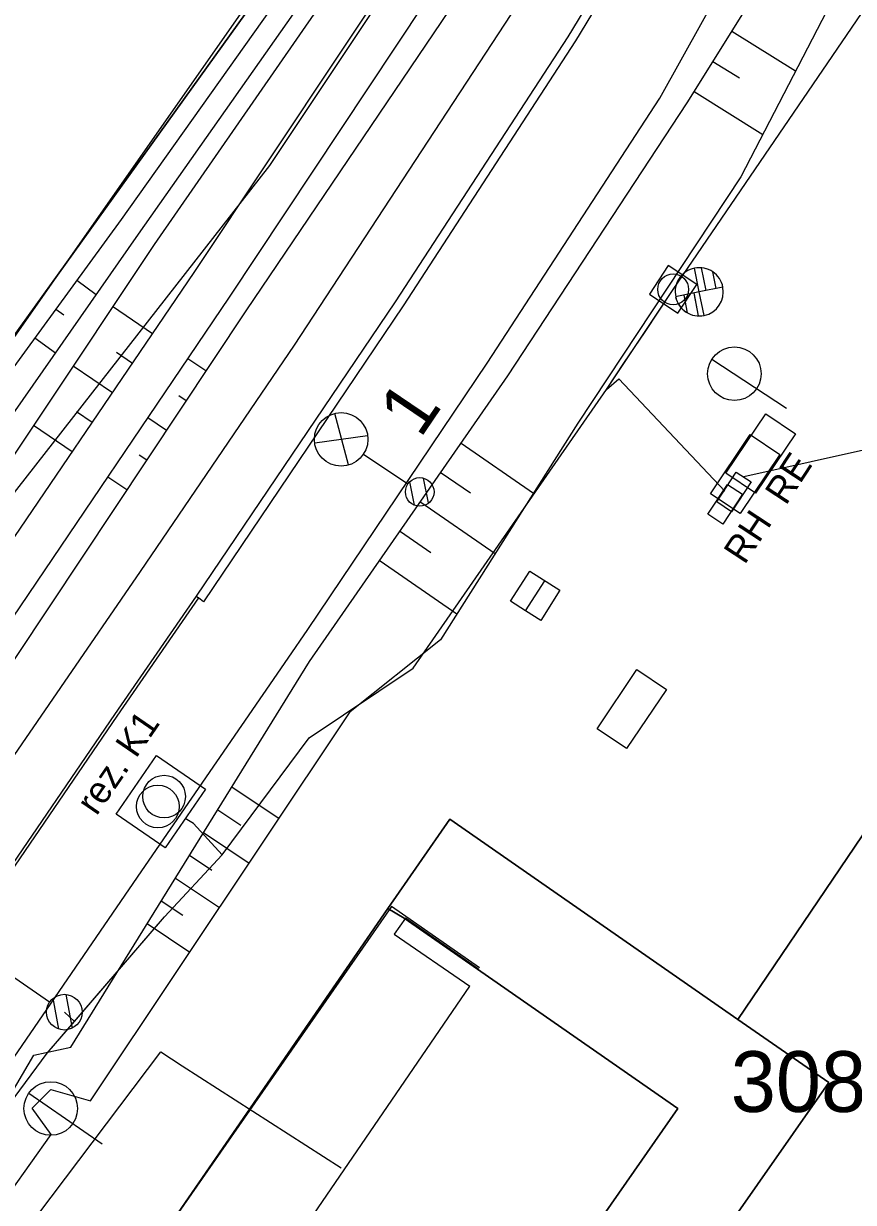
# Model space of a CAD drawing. Extents: x -558195 to -557985, y -1073457 to -1073198.
# Drawn here: x -558098.53 to -558075.28, y -1073355.93 to -1073322.92 of the extents above; entities that cross this region are included whole.
import ezdxf

# ---------------------------------------------------------------- set-up
doc = ezdxf.new("R2010")
doc.units = 0
for name, color, linetype in [('DWG-zabzař', 7, 'Continuous'), ('El2015-Elektro nadzemní', 7, 'Continuous'), ('El2015-Elektro podzemní', 7, 'Continuous'), ('El2015-Nástupiště', 7, 'Continuous'), ('El2015-Sdělovací dálkové podzemní', 7, 'Continuous'), ('El2015-Sdělovací místní podzemní', 7, 'Continuous'), ('El2015-Sdělovací objekt', 7, 'Continuous'), ('El2015-Sonda - šrafa - vrstevnice', 7, 'Continuous'), ('El2015-Terén', 7, 'Continuous'), ('Elektro nadzemní', 7, 'Continuous'), ('Kanalizace nadzemní', 7, 'Continuous'), ('Kolej', 7, 'Continuous'), ('Nástupiště', 7, 'Continuous'), ('Plot - zábradlí', 7, 'Continuous'), ('Přejezd - štěrkové lože', 7, 'Continuous'), ('Sonda - šrafa - vrstevnice', 7, 'Continuous'), ('Stavba', 7, 'Continuous'), ('Svazek obcí údolí Desné', 7, 'Continuous'), ('Svazek obcí-elektro', 7, 'Continuous'), ('Svazek obcí-sdělovací', 7, 'Continuous'), ('Svazek obcí-zabezpečovací', 7, 'Continuous'), ('Terén', 7, 'Continuous'), ('trasa_NN_popisky', 7, 'Continuous'), ('Vedení nerozlišené', 7, 'Continuous'), ('Vedení neurčené', 7, 'Continuous'), ('Vrstva 15', 7, 'Continuous'), ('Vrstva 16', 7, 'Continuous'), ('Vrstva 18', 7, 'Continuous')]:
    doc.layers.add(name, color=color, linetype=linetype)

# ---------------------------------------------------------------- blocks, each defined once
blk = doc.blocks.new('C161_1')
at = {"layer": 'El2015-Sdělovací místní podzemní'}
blk.add_lwpolyline([(-19.93, 33.22), (19.93, 33.22), (19.93, 0), (-19.93, 0)], close=True, dxfattribs=at)
for centre in [(-3.21, 16.51), (3.37, 16.75)]:
    blk.add_circle(centre, 11.96, dxfattribs=at)
blk = doc.blocks.new('C730_1')
at = {"layer": 'El2015-Sdělovací objekt'}
blk.add_lwpolyline([(-9.6, -9.6), (9.6, -9.6), (9.6, 9.6), (-9.6, 9.6)], close=True, dxfattribs=at)
blk.add_circle((0, 0), 8.64, dxfattribs=at)
blk = doc.blocks.new('C178')
at = {"layer": 'El2015-Sdělovací dálkové podzemní'}
for p, q in [((-13.55, -0.04), (-6.78, 6.73)), ((2.2, -2.24), (11.44, 7)), ((-11.88, -6.47), (-2.77, 2.68)), ((6.29, -6.25), (13.38, 0.84))]:
    blk.add_line(p, q, dxfattribs=at)
for points in [[(-9.57, 9.62), (-9.55, 9.59), (-0.13, 0), (-9.72, -9.5)], [(9.46, 9.59), (-0.04, 0), (9.55, -9.5), (9.56, -9.48)], [(9.44, 9.62), (9.46, 9.59)]]:
    blk.add_lwpolyline(points, dxfattribs=at)
for centre, radius, start, end in [((-0.01, 0.01), 13.48, 45.47613, 134.84216), ((-0.11, 0.01), 13.48, 134.52387, 224.76094), ((-0.01, 0.01), 13.48, 315.23906, 45.47613), ((-0.11, 0.01), 13.5, 224.76226, 315.55166)]:
    blk.add_arc(centre, radius, start, end, dxfattribs=at)

msp = doc.modelspace()

# ---------------------------------------------------------------- linework, layer by layer
at = {"layer": 'DWG-zabzař'}
for p, q in [((-558084.66, -1073316.4), (-558091.64, -1073326.89)), ((-558091.64, -1073326.89), (-558100.51, -1073338.24)), ((-558098.13, -1073356.28), (-558094.69, -1073351.72)), ((-558094.69, -1073351.72), (-558094.09, -1073352.11)), ((-558094.09, -1073352.11), (-558089.64, -1073354.97))]:
    msp.add_line(p, q, dxfattribs=at)
at = {"layer": 'El2015-Elektro nadzemní'}
for p, q in [((-558097.804, -1073350.323), (-558100.689, -1073348.34)), ((-558097.542, -1073351.083), (-558097.703, -1073350.218)), ((-558097.167, -1073351.05), (-558097.342, -1073350.109))]:
    msp.add_line(p, q, dxfattribs=at)
for points in [[(-558078.564, -1073335.479), (-558078.146, -1073335.753), (-558078.694, -1073336.589), (-558079.112, -1073336.315), (-558078.564, -1073335.479)], [(-558078.81, -1073335.827), (-558078.392, -1073336.101), (-558078.94, -1073336.937), (-558079.358, -1073336.663), (-558078.81, -1073335.827)]]:
    msp.add_lwpolyline(points, dxfattribs=at)
msp.add_circle((-558097.392, -1073350.606), 0.5, dxfattribs=at)
at = {"layer": 'El2015-Elektro podzemní'}
msp.add_line((-558097.108, -1073350.87), (-558097.392, -1073350.606), dxfattribs=at)
at = {"layer": 'El2015-Nástupiště'}
for points in [[(-558093.699, -1073338.955), (-558095.987, -1073342.272), (-558099.388, -1073347.237), (-558102.768, -1073352.161)], [(-558093.633, -1073339), (-558095.921, -1073342.317), (-558099.322, -1073347.282)], [(-558093.699, -1073338.955), (-558093.633, -1073339), (-558093.633, -1073339)], [(-558100.191, -1073353.885), (-558095.119, -1073346.503), (-558091.122, -1073340.69), (-558090.573, -1073339.885)]]:
    msp.add_lwpolyline(points, dxfattribs=at)
at = {"layer": 'El2015-Sdělovací dálkové podzemní'}
for p, q in [((-558079.731, -1073329.767), (-558079.731, -1073329.767)), ((-558079.545, -1073329.761), (-558079.416, -1073330.394)), ((-558079.231, -1073329.869), (-558079.136, -1073330.338)), ((-558080.038, -1073330.524), (-558079.939, -1073331.016)), ((-558079.758, -1073330.465), (-558079.628, -1073331.105)), ((-558079.466, -1073331.094), (-558079.466, -1073331.094))]:
    msp.add_line(p, q, dxfattribs=at)
for points in [[(-558078.941, -1073330.302), (-558079.6, -1073330.43), (-558079.731, -1073329.767)], [(-558079.466, -1073331.094), (-558079.603, -1073330.433), (-558080.264, -1073330.571)]]:
    msp.add_lwpolyline(points, dxfattribs=at)
for centre, radius, start, end in [((-558079.6, -1073330.43), 0.675, 101.2251, 192.0145), ((-558079.6, -1073330.43), 0.674, 10.9867, 101.2237), ((-558079.603, -1073330.435), 0.674, 191.7019, 281.9389), ((-558079.603, -1073330.435), 0.674, 281.9389, 11.305)]:
    msp.add_arc(centre, radius, start, end, dxfattribs=at)
at = {"layer": 'El2015-Sdělovací objekt'}
msp.add_lwpolyline([(-558080.469, -1073329.699), (-558080.999, -1073330.499), (-558080.199, -1073331.029), (-558079.669, -1073330.229)], close=True, dxfattribs=at)
msp.add_circle((-558080.334, -1073330.364), 0.432, dxfattribs=at)
at = {"layer": 'El2015-Sonda - šrafa - vrstevnice'}
for p, q in [((-558092.7, -1073344.297), (-558091.376, -1073345.182)), ((-558093.095, -1073344.935), (-558092.444, -1073345.37)), ((-558093.491, -1073345.573), (-558092.209, -1073346.429)), ((-558093.886, -1073346.211), (-558093.256, -1073346.632)), ((-558094.281, -1073346.849), (-558093.043, -1073347.676)), ((-558094.676, -1073347.487), (-558094.068, -1073347.893)), ((-558095.071, -1073348.125), (-558093.876, -1073348.924))]:
    msp.add_line(p, q, dxfattribs=at)
at = {"layer": 'El2015-Terén'}
for points in [[(-558100.191, -1073353.885), (-558100.042, -1073354.758), (-558099.266, -1073353.898), (-558099.045, -1073353.167), (-558098.244, -1073351.807), (-558097.213, -1073351.582), (-558090.522, -1073340.781)], [(-558100.875, -1073354.883), (-558100.587, -1073355.931), (-558098.897, -1073355.64), (-558097.764, -1073354.03), (-558098.294, -1073353.295), (-558097.774, -1073352.77), (-558096.662, -1073353.093), (-558089.38, -1073342.195)]]:
    msp.add_lwpolyline(points, dxfattribs=at)
at = {"layer": 'Elektro nadzemní'}
for p, q in [((-558089.426, -1073335.278), (-558089.81, -1073333.836)), ((-558090.373, -1073334.661), (-558088.896, -1073334.455)), ((-558089.012, -1073334.978), (-558087.766, -1073335.813)), ((-558087.584, -1073336.404), (-558087.713, -1073335.753)), ((-558087.188, -1073336.346), (-558087.325, -1073335.653))]:
    msp.add_line(p, q, dxfattribs=at)
for points in [[(-558078.024, -1073336.07), (-558078.854, -1073335.511), (-558077.736, -1073333.852), (-558076.906, -1073334.411), (-558078.024, -1073336.07)], [(-558078.46, -1073336.644), (-558079.29, -1073336.085), (-558078.172, -1073334.426), (-558077.342, -1073334.985), (-558078.46, -1073336.644)], [(-558081.637, -1073343.226), (-558082.467, -1073342.667), (-558081.349, -1073341.008), (-558080.519, -1073341.567), (-558081.637, -1073343.226)]]:
    msp.add_lwpolyline(points, dxfattribs=at)
for centre, radius in [((-558089.636, -1073334.564), 0.749), ((-558087.434, -1073336.036), 0.4), ((-558087.434, -1073336.036), 0.4)]:
    msp.add_circle(centre, radius, dxfattribs=at)
at = {"layer": 'Kanalizace nadzemní'}
msp.add_lwpolyline([(-558084.466, -1073339.369), (-558084.889, -1073339.1), (-558084.352, -1073338.255), (-558083.507, -1073338.792), (-558084.044, -1073339.637), (-558084.466, -1073339.369), (-558083.93, -1073338.523)], dxfattribs=at)
at = {"layer": 'Kolej'}
msp.add_lwpolyline([(-558162.085, -1073435.464), (-558155.66, -1073426.127), (-558147.216, -1073413.854), (-558143.692, -1073408.727), (-558141.06, -1073404.904), (-558137.302, -1073399.438), (-558134.569, -1073395.461), (-558131.717, -1073391.307), (-558124.893, -1073381.375), (-558115.4, -1073367.564), (-558106.183, -1073354.164), (-558097.487, -1073341.511), (-558095.261, -1073338.268), (-558090.946, -1073331.927), (-558084.696, -1073322.399), (-558079.035, -1073313.091), (-558076.876, -1073309.237)], dxfattribs=at)
at = {"layer": 'Nástupiště'}
for points in [[(-558075.504, -1073310.182), (-558077.642, -1073314), (-558083.287, -1073323.291), (-558088.119, -1073330.713), (-558093.699, -1073338.955)], [(-558075.301, -1073310.322), (-558077.424, -1073314.112), (-558083.069, -1073323.403), (-558087.901, -1073330.825), (-558093.497, -1073339.112), (-558093.633, -1073339)], [(-558090.573, -1073339.885), (-558085.54, -1073332.431), (-558080.709, -1073325.01), (-558077.164, -1073318.639)]]:
    msp.add_lwpolyline(points, dxfattribs=at)
at = {"layer": 'Plot - zábradlí'}
msp.add_lwpolyline([(-558081.585, -1073305.993), (-558081.958, -1073306.712), (-558085.995, -1073313.64), (-558091.417, -1073321.151), (-558105.2, -1073340.829), (-558131.731, -1073378.073), (-558133.048, -1073381.894), (-558138.367, -1073389.952)], dxfattribs=at)
at = {"layer": 'Přejezd - štěrkové lože'}
for p, q in [((-558093.424, -1073332.648), (-558093.935, -1073332.308)), ((-558093.977, -1073333.481), (-558094.185, -1073333.343)), ((-558094.531, -1073334.314), (-558095.056, -1073333.965)), ((-558095.085, -1073335.147), (-558095.298, -1073335.005)), ((-558095.638, -1073335.979), (-558096.177, -1073335.621))]:
    msp.add_line(p, q, dxfattribs=at)
for points in [[(-558134.688, -1073392.469), (-558133.239, -1073389.979), (-558128.353, -1073382.563), (-558117.195, -1073366.537), (-558107.127, -1073351.64), (-558099.301, -1073340.237), (-558092.768, -1073330.583), (-558086.524, -1073321.182), (-558080.801, -1073311.959), (-558078.61, -1073308.043)], [(-558078.156, -1073308.355), (-558080.336, -1073312.26), (-558085.948, -1073321.555), (-558092.305, -1073330.965), (-558098.739, -1073340.644), (-558106.694, -1073352.203), (-558116.612, -1073366.808), (-558126.104, -1073380.52), (-558132.827, -1073390.228), (-558134.688, -1073392.469)]]:
    msp.add_lwpolyline(points, dxfattribs=at)
at = {"layer": 'Sonda - šrafa - vrstevnice'}
for p, q in [((-558078.687, -1073323.129), (-558076.903, -1073324.243)), ((-558079.217, -1073323.978), (-558078.475, -1073324.44)), ((-558079.746, -1073324.826), (-558077.825, -1073326.025)), ((-558097.04, -1073330.107), (-558096.498, -1073330.503)), ((-558097.629, -1073330.916), (-558097.406, -1073331.078)), ((-558094.921, -1073331.608), (-558096.038, -1073330.847)), ((-558098.219, -1073331.723), (-558097.644, -1073332.143)), ((-558095.484, -1073332.435), (-558095.927, -1073332.133)), ((-558096.047, -1073333.261), (-558097.148, -1073332.511)), ((-558096.61, -1073334.088), (-558097.047, -1073333.79)), ((-558097.173, -1073334.914), (-558098.259, -1073334.175)), ((-558086.269, -1073334.674), (-558084.247, -1073336.072)), ((-558086.838, -1073335.497), (-558086.016, -1073336.065)), ((-558087.407, -1073336.319), (-558085.319, -1073337.763)), ((-558087.976, -1073337.141), (-558087.127, -1073337.728)), ((-558088.544, -1073337.964), (-558086.391, -1073339.453))]:
    msp.add_line(p, q, dxfattribs=at)
at = {"layer": 'Stavba'}
for points in [[(-558085.764, -1073349.362), (-558088.225, -1073347.646), (-558094.346, -1073356.427), (-558098.392, -1073362.333)], [(-558087.829, -1073347.978), (-558088.146, -1073348.417), (-558086.033, -1073349.879)], [(-558085.79, -1073349.4), (-558087.829, -1073347.978)], [(-558094.346, -1073356.427), (-558091.741, -1073358.211), (-558086.033, -1073349.879)]]:
    msp.add_lwpolyline(points, dxfattribs=at)
at = {"layer": 'Svazek obcí údolí Desné'}
for points in [[(-558167.537, -1073431.708), (-558157.08, -1073415.91), (-558144.45, -1073397.61), (-558143.83, -1073396.83), (-558140.29, -1073392.34), (-558139.67, -1073391.56), (-558138.4, -1073389.94), (-558132.32, -1073380.12), (-558131.71, -1073378.11), (-558099.53, -1073332.65), (-558091.21, -1073321.1), (-558086.89, -1073315.11), (-558086.02, -1073313.63), (-558082.18, -1073306.93), (-558081.607, -1073305.978)], [(-558060.859, -1073320.27), (-558066.64, -1073329.29), (-558067.37, -1073328.67), (-558071.91, -1073335.47), (-558071.45, -1073339.78), (-558072.38, -1073341.74), (-558078.52, -1073350.81), (-558086.59, -1073345.2), (-558088.33, -1073347.7), (-558094.78, -1073357.07), (-558098.42, -1073362.32), (-558098.04, -1073362.58), (-558100.88, -1073366.68), (-558101.24, -1073366.41), (-558106.08, -1073373.34), (-558109.37, -1073371.06), (-558120.48, -1073382.36), (-558123.3, -1073385.22), (-558134.85, -1073401.19), (-558135.09, -1073403.23), (-558138.47, -1073412.32), (-558157.115, -1073438.887)]]:
    msp.add_lwpolyline(points, dxfattribs=at)
at = {"layer": 'Svazek obcí-elektro'}
for p, q in [((-558097.804, -1073350.323), (-558100.689, -1073348.34)), ((-558097.542, -1073351.083), (-558097.703, -1073350.218)), ((-558097.167, -1073351.05), (-558097.342, -1073350.109))]:
    msp.add_line(p, q, dxfattribs=at)
msp.add_lwpolyline([(-558104.377, -1073360.537), (-558097.871, -1073351.756), (-558097.108, -1073350.87), (-558094.584, -1073347.94), (-558092.974, -1073346.202), (-558090.533, -1073342.919), (-558087.618, -1073340.975), (-558082.203, -1073333.171), (-558081.857, -1073332.87), (-558078.884, -1073336.019)], dxfattribs=at)
msp.add_lwpolyline([(-558104.377, -1073360.537), (-558097.871, -1073351.756), (-558097.108, -1073350.87), (-558094.584, -1073347.94), (-558092.974, -1073346.202), (-558090.533, -1073342.919), (-558087.618, -1073340.975), (-558082.203, -1073333.171), (-558081.857, -1073332.87), (-558078.884, -1073336.019)], dxfattribs=at)
msp.add_circle((-558097.392, -1073350.606), 0.5, dxfattribs=at)
at = {"layer": 'Svazek obcí-sdělovací'}
msp.add_line((-558081.857, -1073332.87), (-558078.884, -1073336.019), dxfattribs=at)
for points in [[(-558092.974, -1073346.202), (-558090.533, -1073342.919), (-558087.618, -1073340.975), (-558082.203, -1073333.171), (-558080.334, -1073330.364), (-558074.513, -1073321.837), (-558069.419, -1073314.373)], [(-558092.974, -1073346.202), (-558093.77, -1073345.321), (-558094.003, -1073345.183)]]:
    msp.add_lwpolyline(points, dxfattribs=at)
at = {"layer": 'Svazek obcí-zabezpečovací'}
msp.add_lwpolyline([(-558104.377, -1073360.537), (-558097.871, -1073351.756), (-558094.584, -1073347.94), (-558092.974, -1073346.202), (-558090.533, -1073342.919), (-558087.618, -1073340.975), (-558082.203, -1073333.171), (-558081.697, -1073332.405), (-558081.138, -1073331.577), (-558080.334, -1073330.364), (-558074.513, -1073321.837)], dxfattribs=at)
at = {"layer": 'Terén'}
for points in [[(-558081.18, -1073306.272), (-558083.456, -1073310.395), (-558089.337, -1073319.304), (-558095.797, -1073328.403), (-558102.651, -1073337.801)], [(-558080.693, -1073306.608), (-558082.815, -1073310.544), (-558088.899, -1073319.675), (-558095.32, -1073328.817), (-558102.006, -1073338.385), (-558110.752, -1073350.405)], [(-558080.325, -1073306.861), (-558082.46, -1073310.779), (-558088.525, -1073319.94), (-558094.874, -1073329.104), (-558101.386, -1073338.86), (-558109.505, -1073351.261), (-558119.112, -1073365.018), (-558130.44, -1073381.204), (-558136.541, -1073389.319), (-558138.367, -1073389.952)], [(-558141.446, -1073388.086), (-558138.672, -1073391.073), (-558136.007, -1073391.106), (-558129.583, -1073381.786), (-558118.096, -1073365.959), (-558108.152, -1073351.289), (-558100.315, -1073339.526), (-558093.751, -1073329.892), (-558087.503, -1073320.498), (-558081.802, -1073311.451), (-558079.554, -1073307.392)], [(-558075.447, -1073319.704), (-558075.635, -1073321.794), (-558078.439, -1073327.212), (-558083.002, -1073334.109), (-558086.852, -1073340.18), (-558089.38, -1073342.195)], [(-558090.522, -1073340.781), (-558084.963, -1073332.785), (-558079.942, -1073325.14), (-558076.703, -1073319.95)]]:
    msp.add_lwpolyline(points, dxfattribs=at)
at = {"layer": 'trasa_NN_popisky'}
msp.add_lwpolyline([(-558056.317, -1073323.399), (-558061.372, -1073331.828), (-558078.355, -1073335.616)], dxfattribs=at)
at = {"layer": 'Vedení nerozlišené'}
for p, q in [((-558079.245, -1073332.315), (-558077.155, -1073333.686)), ((-558098.391, -1073352.878), (-558096.331, -1073354.294))]:
    msp.add_line(p, q, dxfattribs=at)
for centre in [(-558078.618, -1073332.726), (-558097.773, -1073353.303)]:
    msp.add_circle(centre, 0.75, dxfattribs=at)
at = {"layer": 'Vrstva 15'}
for points in [[(-558167.537, -1073431.708), (-558157.08, -1073415.91), (-558144.45, -1073397.61), (-558143.83, -1073396.83), (-558140.29, -1073392.34), (-558139.67, -1073391.56), (-558138.4, -1073389.94), (-558132.32, -1073380.12), (-558131.71, -1073378.11), (-558099.53, -1073332.65), (-558091.21, -1073321.1), (-558086.89, -1073315.11), (-558086.02, -1073313.63), (-558082.18, -1073306.93), (-558081.607, -1073305.978)], [(-558060.859, -1073320.27), (-558066.64, -1073329.29), (-558067.37, -1073328.67), (-558071.91, -1073335.47), (-558071.45, -1073339.78), (-558072.38, -1073341.74), (-558078.52, -1073350.81), (-558086.59, -1073345.2), (-558088.33, -1073347.7), (-558094.78, -1073357.07), (-558098.42, -1073362.32), (-558098.04, -1073362.58), (-558100.88, -1073366.68), (-558101.24, -1073366.41), (-558106.08, -1073373.34), (-558109.37, -1073371.06), (-558120.48, -1073382.36), (-558123.3, -1073385.22), (-558134.85, -1073401.19), (-558135.09, -1073403.23), (-558138.47, -1073412.32), (-558157.115, -1073438.887)], [(-558056.484, -1073323.284), (-558060.65, -1073327.54), (-558061.08, -1073328.44), (-558065.9, -1073348.86), (-558066.74, -1073350.64), (-558083.8, -1073372.96), (-558092.4, -1073382.52), (-558096.11, -1073380.17), (-558087.9, -1073369.62), (-558075.97, -1073352.58), (-558078.52, -1073350.81), (-558072.38, -1073341.74), (-558071.45, -1073339.78), (-558071.91, -1073335.47), (-558067.37, -1073328.67), (-558066.64, -1073329.29), (-558060.859, -1073320.27)]]:
    msp.add_lwpolyline(points, dxfattribs=at)
for points in [[(-558139.67, -1073391.56), (-558140.9, -1073387.37), (-558143.89, -1073378.07), (-558101.27, -1073319.14), (-558106.1, -1073313.94), (-558108.58, -1073311.13), (-558110.09, -1073309.68), (-558108.61, -1073307.47), (-558103.03, -1073311.24), (-558100.91, -1073308.09), (-558098.7, -1073309.62), (-558100.86, -1073312.72), (-558101.25, -1073313.61), (-558091.21, -1073321.1), (-558099.53, -1073332.65), (-558131.71, -1073378.11), (-558132.32, -1073380.12), (-558138.4, -1073389.94)], [(-558086.24, -1073361.96), (-558080.2, -1073353.3), (-558087.87, -1073347.97), (-558088.33, -1073347.7), (-558086.59, -1073345.2), (-558078.52, -1073350.81), (-558075.97, -1073352.58), (-558087.9, -1073369.62), (-558096.11, -1073380.17), (-558097.38, -1073379.37), (-558101.16, -1073376.75), (-558106.08, -1073373.34), (-558101.24, -1073366.41), (-558100.88, -1073366.68), (-558093.95, -1073371.49), (-558091.09, -1073367.38), (-558089.54, -1073368.47), (-558085.38, -1073362.53)], [(-558094.78, -1073357.07), (-558088.33, -1073347.7), (-558087.87, -1073347.97), (-558080.2, -1073353.3), (-558086.24, -1073361.96), (-558085.38, -1073362.53), (-558089.54, -1073368.47), (-558091.09, -1073367.38), (-558093.95, -1073371.49), (-558100.88, -1073366.68), (-558098.04, -1073362.58), (-558098.42, -1073362.32)]]:
    msp.add_lwpolyline(points, close=True, dxfattribs=at)
at = {"layer": 'Vrstva 16'}
msp.add_lwpolyline([(-558098.42, -1073362.32), (-558094.78, -1073357.07), (-558088.33, -1073347.7), (-558087.87, -1073347.97), (-558080.2, -1073353.3), (-558086.24, -1073361.96), (-558085.38, -1073362.53), (-558089.54, -1073368.47), (-558091.09, -1073367.38), (-558093.95, -1073371.49), (-558100.88, -1073366.68), (-558098.04, -1073362.58)], close=True, dxfattribs=at)

# ---------------------------------------------------------------- block references
at = {"layer": 'Svazek obcí-sdělovací'}
for name, p, xscale, yscale, rotation in [('C178', (-558079.604, -1073330.435), 0.05, 0.05000000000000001, -123.53719177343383), ('C730_1', (-558080.334, -1073330.364), 0.05, 0.05000000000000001, -123.53719162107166), ('C161_1', (-558094.003, -1073345.183), 0.049999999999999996, 0.05, 55.50051041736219)]:
    msp.add_blockref(name, p, dxfattribs=dict(at, xscale=xscale, yscale=yscale, rotation=rotation))

# ---------------------------------------------------------------- texts
at = {"layer": 'El2015-Elektro nadzemní'}
for s, p in [('RE', (-558077.176, -1073336.437)), ('RH', (-558078.332, -1073338.097))]:
    msp.add_text(s, height=0.75, rotation=56.7367, dxfattribs=at).set_placement(p)
at = {"layer": 'Svazek obcí-sdělovací'}
msp.add_text('rez. K1', height=0.75, rotation=55.5005, dxfattribs=at).set_placement((-558096.491, -1073345.129))
at = {"layer": 'Vedení neurčené'}
msp.add_text('1', height=1.5, rotation=55.8849, dxfattribs=at).set_placement((-558087.419, -1073334.562))
at = {"layer": 'Vrstva 18'}
msp.add_text('308/2', height=1.7, dxfattribs=at).set_placement((-558078.72, -1073353.4))

doc.saveas('drawing.dxf')
